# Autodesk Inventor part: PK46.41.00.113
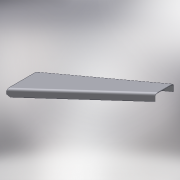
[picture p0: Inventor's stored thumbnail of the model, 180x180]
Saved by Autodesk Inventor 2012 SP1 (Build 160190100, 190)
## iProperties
Created: 2005-07
Part Number: PK46.41.00.113
Material: Steel, Mild
Document SubType Name: Листовой материал
Designer: PVitaliy
Manufacturer: Standard
Standards Organization: Custom
Density: 7.86 g/cm^3
Sheet Metal Rule: По умолчанию
Author: PVitaliy
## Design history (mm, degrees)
node "Грань1"
  sketch "Эскиз2"
    geometry: L1 (0, 0)-(0, 120); L2 (0, 120)-(300, 340); L3 (300, 340)-(300, 270); L4 (300, 270)-(0, 0)
    constraints: 8 end point, 2 vertical, 1 other
    dimensions: "d0" = 120 distance of L1.start L1.end; "d1" = 70 distance of L2.end L3.end; "d2" = 340 vertical distance of L2.end L1.start; "d3" = 300 distance between parallel lines of L3 L1
node "Фланец1"
node "Фланец2"
feature "Угловая фаска1" dims "d23" = 10, "d24" = 6, angle "d25" = 45 deg
body "Solid1"
feature "Плакирование1" dims "Толщина" = 3
sketch "Эскиз3"
  geometry: L1 (-372.022, 0)-(-372.022, -24); L2 (-372.022, -24)-(0, -24); 2 other entities
  constraints: 4 end point, 4 other
feature "Плакирование2" dims "d5" = 3 (= Ширина_просечки), "d7" = 6 (= Минимальный_остаток), "d9" = 24, "d10" = 90 deg, "d11" = 5 (= Радиус_гибки), "Толщина" = 3
feature "Изгиб1" dims "d5" = 3 (= Ширина_просечки), "d6" = 1.5 (= Глубина_просечки), "d7" = 6 (= Минимальный_остаток), "d8" = 5 (= Радиус_гибки), "d9" = 24, "d10" = 90 deg, "d11" = 5 (= Радиус_гибки), "Толщина" = 3, "Зазор_стыка" = 0.01
sketch "Эскиз4"
  geometry: L1 (-403.609, 0)-(-403.609, -24); L2 (-403.609, -24)-(0, -24); 2 other entities
  constraints: 4 end point, 4 other
feature "Плакирование3" dims "d12" = 3 (= Ширина_просечки), "d14" = 6 (= Минимальный_остаток), "d16" = 24, "d17" = 90 deg, "d18" = 5 (= Радиус_гибки), "Толщина" = 3
feature "Изгиб2" dims "d12" = 3 (= Ширина_просечки), "d13" = 1.5 (= Глубина_просечки), "d14" = 6 (= Минимальный_остаток), "d15" = 5 (= Радиус_гибки), "d16" = 24, "d17" = 90 deg, "d18" = 5 (= Радиус_гибки), "Толщина" = 3, "Зазор_стыка" = 0.01
other parameters: "Радиус_гибки" = 5, "Ширина_просечки" = 3 (= Толщина), "Глубина_просечки" = 1.5 (= 0.5 x Толщина), "Размер_высечки" = 12 (= 4 x Толщина), "Минимальный_остаток" = 6 (= 2 x Толщина), "Радиус_перехода" = 5 (= Радиус_гибки), "d4" = 5 (= Радиус_гибки), "JacobiRadiusSize" = 3 (= Толщина), "GapSize" = 3 (= Толщина)
